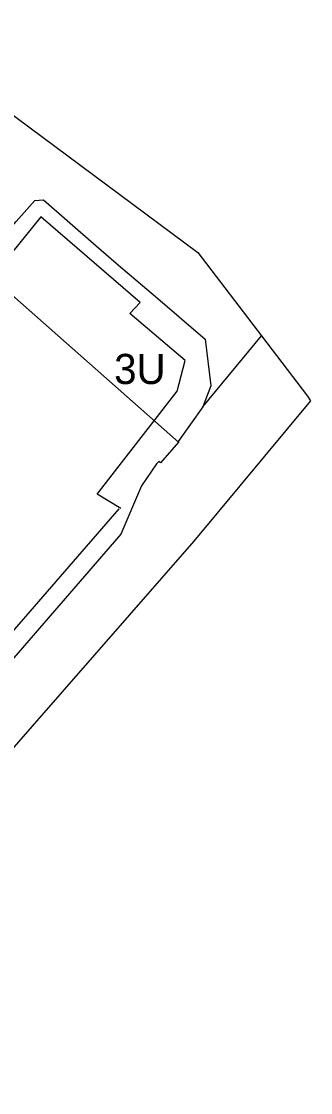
# Model space of a CAD drawing. Extents: x 7426210 to 7427579, y 5548413 to 5549685.
# Drawn here: x 7427118.1 to 7427214.1, y 5548618 to 5548973.3 of the extents above; entities that cross this region are included whole.
import ezdxf

# ---------------------------------------------------------------- set-up
doc = ezdxf.new("R2010")
doc.units = 0
for name, color, linetype in [('linie_rozgraniczajace', 7, 'Continuous'), ('linie_zabudowy_nieprzekraczalne', 7, 'Continuous'), ('linie_zabudowy_obowiazujace', 7, 'Continuous'), ('oznaczenia_przeznaczen', 7, 'Continuous')]:
    doc.layers.add(name, color=color, linetype=linetype)

msp = doc.modelspace()

# ---------------------------------------------------------------- linework, layer by layer
at = {"layer": 'linie_rozgraniczajace'}
for p, q in [((7427103.85, 5548892.38), (7427170.23, 5548833.74)), ((7427178.29, 5548845.49), (7427197.78, 5548869.04)), ((7427213.02, 5548848.97), (7427214.1, 5548847.4))]:
    msp.add_line(p, q, dxfattribs=at)
for points in [[(7427073.43, 5548973.27), (7427176.69, 5548896.63), (7427197.78, 5548869.04), (7427213.08, 5548849.03), (7427213.02, 5548848.97)], [(7427125.5, 5548914.1), (7427133.33, 5548907.25), (7427142.99, 5548898.8), (7427149.56, 5548893.06), (7427151.81, 5548891.16), (7427162.67, 5548882), (7427179.08, 5548867.84), (7427181.01, 5548852.4), (7427178.29, 5548845.49), (7427170.15, 5548833.9), (7427170.28, 5548833.79), (7427170.23, 5548833.74), (7427164.3, 5548826.85), (7427163.75, 5548827.34), (7427162.99, 5548826.5), (7427157.96, 5548819.2), (7427151.08, 5548803.16), (7427112.12, 5548758.07), (7427033.49, 5548667.27), (7427005.36, 5548634.62), (7426991.04, 5548617.99)], [(7427103.85, 5548892.38), (7427116.37, 5548906.9), (7427122.6, 5548913.85), (7427125.5, 5548914.1)], [(7427214.1, 5548847.4), (7427175.3, 5548800.83), (7427120.9, 5548738.6), (7427069.59, 5548679.9)]]:
    msp.add_lwpolyline(points, dxfattribs=at)
at = {"layer": 'linie_zabudowy_nieprzekraczalne'}
msp.add_line((7427124.63, 5548908.44), (7427107.73, 5548887.67), dxfattribs=at)
msp.add_lwpolyline([(7427151.13, 5548811.75), (7427143.3, 5548816.51), (7427169.79, 5548850.65), (7427172.43, 5548860.83), (7427172.43, 5548860.83), (7427154.09, 5548876.34), (7427157.53, 5548880.09), (7427124.63, 5548908.44)], dxfattribs=at)
at = {"layer": 'linie_zabudowy_obowiazujace'}
msp.add_lwpolyline([(7426999.5, 5548637.91), (7427031.6, 5548673.89), (7427108.64, 5548763.35), (7427150.54, 5548811.58)], dxfattribs=at)

# ---------------------------------------------------------------- texts
at = {"layer": 'oznaczenia_przeznaczen'}
msp.add_text('3U', height=10, dxfattribs=at).set_placement((7427148.91, 5548853))

doc.saveas('drawing.dxf')
